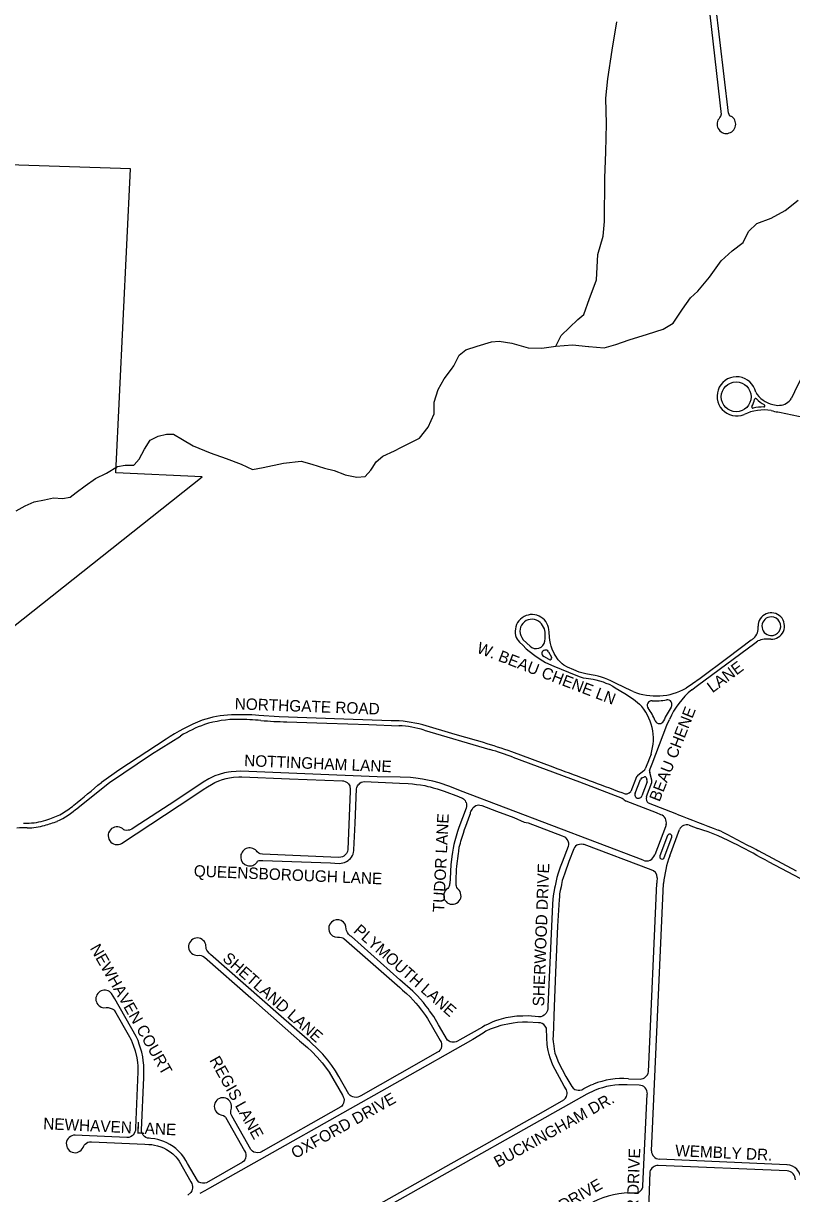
# Model space of a CAD drawing. Extents: x 0 to 712119, y 0 to 761125.
# Drawn here: x 662940 to 666284, y 723620 to 728717 of the extents above; entities that cross this region are included whole.
import ezdxf

# ---------------------------------------------------------------- set-up
doc = ezdxf.new("R2010")
doc.units = 0
for name, color, linetype in [('city boundary', 7, 'Continuous'), ('PAVED ROADS', 7, 'Continuous'), ('stream or creek', 7, 'Continuous'), ('street names', 7, 'Continuous')]:
    doc.layers.add(name, color=color, linetype=linetype)

msp = doc.modelspace()

# ---------------------------------------------------------------- linework, layer by layer
at = {"layer": 'city boundary'}
msp.add_lwpolyline([(661591.7, 725082), (661920.9, 725330.1), (662157.8, 725508.7), (662199.4, 725538.3), (663717.4, 726742.4), (663342.2, 726759.2), (663405.6, 728083), (662077.3, 728127.4), (662054.4, 728128.2), (662062.2, 728326.3), (661826.3, 728333.2), (661818.5, 728136.1), (660757.1, 728171.7), (660784.9, 728985.9), (660790.2, 729140.5), (660790.4, 729140.4), (660803.1, 729516.9), (659488, 729573.5)], dxfattribs=at)
at = {"layer": 'PAVED ROADS'}
for points in [[(665878, 729203.3), (665978.5, 728320.5)], [(666010, 728325.5), (665934.5, 728966.8)], [(665594.3, 725806.3), (665587, 725809.2), (665520.4, 725841.9), (665509, 725848), (665497.3, 725853.9), (665484.8, 725859.1), (665470.3, 725865.4), (665456.7, 725869.5), (665441.7, 725873.9), (665429.8, 725876.7), (665412.1, 725879.5), (665389.2, 725883.6), (665377.3, 725886.3), (665360.1, 725891.7), (665336, 725901.8), (665308.2, 725913), (665292.1, 725921.5), (665285.3, 725928), (665276.4, 725936.3), (665268.6, 725945.4), (665255.1, 725964.9), (665250.9, 725972.7), (665241.9, 725991.5), (665237.6, 726004.8), (665234.2, 726015.5), (665232.3, 726030.3), (665230.9, 726043.4), (665229.4, 726065.2), (665227.7, 726077.6), (665225.7, 726085.5), (665223.2, 726094.1)], [(665085.7, 726041.9), (665089.3, 726035), (665093.4, 726028.8), (665100, 726022.2), (665113.5, 726008.1), (665129.1, 725993.4), (665142.2, 725982.5), (665166.9, 725963.2), (665189.1, 725948), (665212.6, 725933.8), (665248.8, 725918), (665345.2, 725878.8), (665363.4, 725871.4), (665377.3, 725867.2), (665389.3, 725865.6), (665420.9, 725860.5), (665432.1, 725858.1), (665448.1, 725853.5), (665463.3, 725848.7), (665476.2, 725843.8), (665490.3, 725838.6), (665506.1, 725829.6), (665516.1, 725823.5), (665557.7, 725798.9), (665596.7, 725773.6), (665622.1, 725752.3)], [(665109.5, 726042.5), (665115.5, 726032), (665145.5, 726005)], [(665109.5, 726042.5), (665109.5, 726042.5)], [(666109, 726030.1), (666006.9, 725953.4), (665886.7, 725863.6), (665853.2, 725839.9), (665824.8, 725821)], [(665850, 725813.8), (665874.9, 725832.8), (666123.8, 726016.8), (666137.5, 726027)], [(665228.9, 725946.3), (665205.1, 725959.7)], [(665225.4, 725980.3), (665239.1, 725956.6)], [(665228.9, 725946.3), (665228.9, 725946.3)], [(665676.8, 725766.4), (665676.8, 725766.4)], [(664540.5, 725679.5), (664335, 725686.5), (664052.5, 725697), (663964.5, 725703)], [(664086, 725674.5), (664260.5, 725668.5), (664443.5, 725662.5), (664575, 725658)], [(664819.4, 725619.7), (664678.7, 725661.2)], [(665666.3, 725462.8), (665677.7, 725491.5), (665741.4, 725660.1), (665752.9, 725684.8)], [(663177.5, 725301), (663314.5, 725411), (663497, 725534), (663623, 725613)], [(664684.5, 725638.2), (664971.1, 725554.1)], [(663560.5, 725599), (663354.5, 725464.5), (663279, 725411)], [(665246.5, 725476.9), (665065.7, 725544.8)], [(665071.3, 725520.7), (665361, 725414.1), (665546.4, 725342.8)], [(665672.6, 725534.2), (665666.4, 725516.4), (665658.8, 725497.3), (665647.4, 725470.7)], [(665638.7, 725072.3), (664843.5, 725375), (664796.5, 725393), (664750, 725408.5), (664722, 725416), (664699.5, 725421), (664678, 725425.5), (664648.5, 725429.5), (664625, 725432.5), (664579.5, 725434.5), (664479.5, 725436), (664164.5, 725448.5), (663886, 725459.5), (663866.5, 725459), (663844, 725457), (663832.5, 725456), (663814.5, 725452.5), (663792, 725446), (663773, 725439), (663747, 725426.5), (663722, 725411.5), (663598.5, 725329.5), (663422, 725214), (663412, 725208), (663404, 725204.5), (663400.9, 725203.2), (663396, 725202.5), (663388.5, 725202), (663381, 725203.5), (663376.5, 725205)], [(665641.1, 725461.3), (665614.5, 725441.8)], [(665676.2, 725421.2), (665667.2, 725453.7)], [(663367, 725145), (663681.5, 725353), (663722, 725379.5), (663741.5, 725392), (663758, 725402), (663773, 725410.5), (663790.5, 725418), (663806, 725423.5), (663822.5, 725428.5), (663837, 725431.5), (663855, 725434), (663877.5, 725436), (663890, 725435.5), (664097.5, 725427), (664328.5, 725418.5), (664334, 725417.5), (664341, 725415.5), (664349.5, 725410.5), (664355, 725405), (664358.5, 725400), (664360.5, 725396), (664361.5, 725391.5), (664362.5, 725385), (664363, 725378.5), (664363, 725373.5), (664352.5, 725119), (664351, 725109.5), (664346.5, 725101.5), (664341, 725095), (664334.5, 725089.5), (664328.5, 725087), (664321.5, 725085), (664312, 725084), (663980, 725098), (663970, 725100), (663964.5, 725102.5), (663958, 725108), (663954, 725113)], [(663957, 725064), (663958.1, 725065.7), (663959.5, 725067.5), (663962, 725069), (663966.5, 725070.5), (663971, 725071), (663976.5, 725071.5), (663982.5, 725071), (664276.5, 725060), (664315, 725058.5), (664323.5, 725059), (664330.5, 725060.5), (664338, 725062.5), (664346.5, 725066), (664353.5, 725070.5), (664358.5, 725075), (664363.5, 725079.5), (664367.5, 725085), (664372, 725092), (664375, 725099), (664377, 725106.5), (664378.5, 725113.5), (664379, 725117.5), (664383.5, 725234), (664390, 725383), (664391.5, 725389), (664394, 725395.5), (664397, 725400.5), (664401, 725404), (664405, 725408), (664410, 725411.5), (664417.5, 725414), (664423, 725414.5), (664577.5, 725408), (664615, 725406), (664633.5, 725404.5), (664650.5, 725402.5), (664668, 725400), (664687, 725397), (664700, 725393.5), (664711, 725391), (664724, 725387.5), (664740.5, 725382.5), (664759, 725377), (664771.5, 725372.5), (664833.5, 725349.5), (664840.5, 725347), (664851, 725342.5), (664855.5, 725340), (664859, 725336.5), (664862.5, 725331.5), (664865, 725327), (664867, 725323), (664868.5, 725317.5), (664869.5, 725312), (664869, 725305.5), (664867.5, 725299.5), (664835.5, 725215), (664829, 725196.5), (664823.5, 725176.5), (664817.5, 725156.5), (664814, 725140), (664810.5, 725124.5), (664807.5, 725107.5), (664804.5, 725088), (664803, 725075), (664800.5, 725053.5), (664798, 724991.5), (664796, 724971.5), (664795.5, 724967.5), (664794.5, 724963), (664793, 724958.5), (664790, 724953), (664787, 724949.5), (664781, 724944.5)], [(665609.4, 725435), (665584.7, 725371.4)], [(665602.9, 725363.8), (665626.3, 725423.1)], [(665654.9, 725413.2), (665632.8, 725352.3)], [(665634.4, 725431.1), (665644.7, 725435)], [(665651.1, 725432.2), (665654.7, 725423.3)], [(665652.3, 725348.9), (665675.6, 725410.3)], [(665550.6, 725363.5), (665527.5, 725371.9)], [(664836.5, 724941.5), (664830.5, 724948), (664827.5, 724953.5), (664825, 724959), (664824, 724964), (664823.5, 724969), (664823.5, 724980), (664824.5, 724999), (664825, 725017), (664826, 725032), (664827, 725046.5), (664833.5, 725101.5), (664835, 725110.5), (664837.5, 725129), (664840, 725137.5), (664842.5, 725147), (664844.5, 725155.5), (664847, 725164), (664851.5, 725177), (664855.5, 725190), (664860.5, 725206.5), (664865.5, 725220.5), (664884, 725269), (664886, 725275), (664887, 725282), (664887.5, 725284), (664893.5, 725293), (664898.5, 725301.5), (664903.5, 725306.5), (664909, 725310.5), (664915, 725312.5), (664920.5, 725313), (664927, 725312.5), (664935, 725311), (665000, 725286), (665075, 725257.5), (665119.5, 725238.5), (665137.5, 725235.5), (665286, 725178), (665292.5, 725175), (665298, 725172), (665302.5, 725167), (665306.5, 725162), (665310, 725156), (665312.5, 725148.5), (665312.5, 725140.5), (665311, 725132.5), (665285, 725063.5), (665276.5, 725042), (665268, 725015), (665262.5, 724996.5), (665255, 724961), (665252, 724950.5), (665250, 724939.5), (665248, 724925.5), (665245.5, 724904), (665243, 724878.5), (665223.5, 724435), (665222.5, 724424.5), (665221, 724417.5), (665218.5, 724411), (665216, 724406), (665212, 724401.5), (665206.5, 724397), (665200, 724393), (665192.5, 724390.5), (665182.5, 724390.5), (665137.5, 724394), (665114, 724393), (665100, 724392.5), (665088.5, 724393), (665077.5, 724391.5), (665061, 724389), (665050, 724387.5), (665039.5, 724385), (665030, 724382.5), (665020, 724380), (665009.5, 724377), (664995.5, 724372.5), (664984, 724368), (664972.5, 724363), (664960.5, 724357), (664949, 724351.5), (664938.5, 724345.5), (664840, 724290), (664829.5, 724284), (664824, 724281.5), (664816.5, 724280), (664810, 724279.5), (664804.5, 724280), (664798.5, 724281.5), (664793, 724283.5), (664786.5, 724289), (664747.5, 724354.5), (664726, 724391), (664708.5, 724416.5), (664702, 724425.5), (664692, 724438.5), (664681, 724452.5), (664667.5, 724468), (664655, 724481.5), (664645, 724491.5), (664635, 724501.5), (664578.8, 724551.6), (664367.6, 724739.6), (664362.4, 724743.2), (664355, 724750.1), (664350.3, 724757.7), (664346.5, 724765.5), (664345, 724772)], [(665785.2, 725273), (665661.7, 725320.1)], [(665738.5, 725227.9), (665735, 725217.7), (665688.3, 725095.4)], [(665753.7, 725091.7), (665795.8, 725205.8)], [(665838.5, 725224.4), (665875.9, 725210.5)], [(665744.2, 725179.7), (665711.2, 725090.6)], [(665729.8, 725083.5), (665762.9, 725172.5)], [(665672.5, 725030), (665381.5, 725140.5), (665377.5, 725141), (665369.5, 725141.5), (665361.5, 725141), (665353.5, 725139.5), (665349, 725137.5), (665344, 725133), (665339.5, 725128), (665336.5, 725122), (665314.5, 725067), (665297, 725015.5), (665290, 724995.5), (665286, 724983.5), (665282, 724967), (665280.5, 724956.5), (665276.5, 724939.5), (665274, 724926), (665273.5, 724911.5), (665272, 724901.5), (665265.5, 724785.5), (665256.5, 724583), (665250.5, 724434.5), (665246, 724307.5), (665245.5, 724293.5), (665246.5, 724280.5), (665248.5, 724263), (665251, 724248.5), (665254, 724232), (665258, 724221.5), (665270, 724191), (665302, 724130.5), (665327, 724086.5), (665333, 724079), (665341, 724074), (665347.5, 724072), (665355, 724070.5), (665363, 724070), (665371.5, 724072.5), (665379.5, 724077.5), (665388.5, 724082.5), (665412.2, 724093.3), (665421.3, 724097.2)], [(666305.7, 725024), (666140.4, 725112.3)], [(666182.3, 725066.5), (666350.6, 724977.3), (666485.1, 724907.2)], [(665661, 724150.6), (665698.1, 724972.6)], [(665674.3, 723806.7), (665726.8, 724970.5)], [(664306.5, 724736.5), (664311.1, 724736.6), (664316.2, 724736.9), (664324.1, 724735.9), (664330.4, 724734), (664335.3, 724731.6), (664578.6, 724517.5), (664590.5, 724506), (664607.5, 724491), (664623, 724476.5), (664636, 724462.5), (664648, 724450), (664658.5, 724438), (664673, 724419.5), (664681.5, 724408), (664691, 724395), (664699.5, 724382.5), (664749, 724296.5), (664754.5, 724286.5), (664758, 724279.5), (664760, 724274), (664760.5, 724267), (664760, 724260.5), (664758.5, 724254), (664756.5, 724249.5), (664753.5, 724244.5), (664749, 724239.5), (664743.2, 724235.6), (664577.8, 724141.4)], [(664577.8, 724141.4), (664409.5, 724046.2), (664403, 724042.9), (664395.7, 724040.1), (664389.2, 724038.9), (664380.2, 724039.5), (664373.3, 724041.2), (664367.2, 724043.7), (664361.7, 724047.8), (664357.2, 724052.7), (664312.7, 724130.5), (664298, 724154.1), (664282, 724177.7), (664264.7, 724200.5), (664243.3, 724226.6), (664224.6, 724246.5), (664186.8, 724282.2), (664049.7, 724402.2), (663754.4, 724661.7), (663748, 724667.2), (663742.4, 724673.9), (663738.3, 724680.2), (663735.8, 724686.8), (663735.1, 724692.3), (663734.3, 724700.1), (663733.5, 724704.5)], [(663698, 724657.5), (663707.5, 724658), (663714, 724657), (663720.5, 724654.5), (663727.5, 724650.5), (663930, 724472.5), (664142, 724286), (664176, 724257), (664195, 724239), (664219, 724214), (664240, 724189.5), (664255.5, 724170), (664270.5, 724148.5), (664329, 724048), (664332, 724041.5), (664334.5, 724035.5), (664335.5, 724028.5), (664334.5, 724021), (664333, 724013.5), (664330, 724007.5), (664325.5, 724001.5), (664322, 723997.5), (663984, 723806.5), (663979.5, 723803.5), (663970.5, 723799.5), (663960, 723798), (663951, 723798.5), (663943, 723801), (663936.5, 723804.5), (663929.5, 723812), (663847, 723958), (663843, 723967.5), (663842, 723972), (663842, 723977), (663842, 723981), (663843.5, 723986), (663844.9, 723992), (663845.5, 723996)], [(663799, 723963.5), (663804, 723962), (663810.5, 723959.5), (663816, 723956), (663819.5, 723953), (663902.5, 723806), (663906, 723798.5), (663908, 723791), (663908, 723782.5), (663906.5, 723774.5), (663903.5, 723767.5), (663899, 723761.5), (663893.5, 723756.5), (663736.5, 723667), (663729, 723665), (663719.5, 723665), (663711.5, 723666.5), (663703.5, 723670.5), (663697, 723676.5), (663654.5, 723750.5), (663647, 723764), (663637.5, 723778.5), (663627.5, 723792), (663615, 723805), (663603.5, 723816), (663592, 723824.5), (663577.5, 723834), (663564.5, 723841.5), (663551, 723847), (663538.5, 723851.5), (663525, 723856), (663512, 723858.5), (663494.5, 723860.5), (663487, 723861), (663480.5, 723862), (663473, 723864.5), (663466.5, 723869), (663461.5, 723875), (663456.5, 723883), (663454, 723890), (663453.5, 723896.5), (663464, 724125), (663464.5, 724143), (663464.5, 724163.5), (663464, 724179.5), (663461.5, 724200), (663459, 724215.5), (663454.5, 724236), (663450, 724253), (663444, 724270.5), (663438.5, 724286.5), (663430.5, 724304), (663337, 724468.5), (663323.5, 724491)], [(663290, 724429.5), (663299.5, 724430), (663308.5, 724430), (663318, 724428), (663326, 724425), (663331.5, 724422), (663335, 724418.5), (663342, 724407.5), (663396, 724313), (663408, 724290), (663418, 724267), (663425.5, 724242.5), (663433, 724211.5), (663436, 724191), (663437.5, 724177), (663438, 724163.5), (663438, 724151), (663428, 723906), (663427.5, 723901), (663427, 723895), (663425, 723888.5), (663422, 723882), (663418, 723876.5), (663412.5, 723871.5), (663405.5, 723867.5), (663398.5, 723865), (663390, 723864.5), (663196, 723873.5), (663164.5, 723875)], [(664227.7, 723427.6), (664578.6, 723624.7), (664779.3, 723738), (664947.4, 723832.9), (665098.1, 723918.1), (665203.8, 723978), (665292.8, 724028.9), (665299.3, 724035.7), (665304.4, 724043.1), (665306.2, 724048.5), (665307.9, 724055.2), (665307.6, 724061), (665306.5, 724066.8), (665304.4, 724071.3), (665294.8, 724088.5), (665244.9, 724180), (665239.1, 724194.9), (665233.1, 724211), (665228.7, 724226.2), (665224.8, 724242.6), (665222.1, 724258.3), (665220.2, 724270.5), (665218.2, 724296.6), (665217.3, 724340.1), (665211.6, 724349.8), (665205.9, 724356.2), (665198.6, 724360.5), (665191.5, 724363.1), (665183.1, 724364.3), (665134.2, 724366.4), (665112.2, 724366.2), (665090.4, 724364.6), (665071.7, 724362.6), (665048.9, 724358.5), (665033.6, 724355.4), (665019.1, 724351.7), (664998, 724344.7), (664972.4, 724335.6), (664953.5, 724327), (664941.4, 724319.1), (664896.1, 724291.1), (664578.6, 724111.6), (663749.1, 723643.1), (663729.6, 723632.3), (663707.8, 723619.7)], [(665620.4, 724092.2), (665568.7, 724093.7)], [(665573.9, 724120.5), (665624.6, 724118.8)], [(665392.5, 724053.4), (664578.7, 723594.7), (664190.1, 723375.9), (664170.3, 723364), (664155.6, 723353.4), (664137, 723340), (664119, 723324), (664102.5, 723306.5), (664085.5, 723286.5), (664067.5, 723261.5), (664048.5, 723230), (663998, 723144.5), (663986, 723124.5), (663965, 723088.5)], [(665426.5, 724069.6), (665392.5, 724053.4)], [(665637.4, 723653.9), (665656.3, 724053.7)], [(663202, 723827.5), (663204, 723831), (663208.5, 723835.5), (663214, 723839.5), (663220.5, 723843.5), (663227, 723845), (663235.5, 723845), (663468, 723835), (663486, 723834), (663498, 723833.5), (663510.5, 723831.5), (663523.5, 723828.5), (663537.5, 723824), (663549.5, 723819), (663562.5, 723812.5), (663578.5, 723802.5), (663590.5, 723793), (663603, 723780.5), (663611, 723771.5), (663617.5, 723761.5), (663668.5, 723671.5), (663673, 723663.5), (663675, 723658.5), (663676, 723650.5), (663676.5, 723644), (663675, 723638), (663673, 723631.5), (663668, 723625), (663655.5, 723612.5)], [(666264.5, 723744.9), (665708.7, 723769.7)], [(666265, 723718.9), (665704.1, 723743)], [(665666.9, 723714.6), (665655.3, 723384.7)], [(665666.9, 723714.6), (665666.9, 723714.6)]]:
    msp.add_lwpolyline(points, dxfattribs=at)
msp.add_circle((666043.5, 727090.5), 65, dxfattribs=at)
for centre, radius, start, end in [((666000.6, 728278), 40.4, 137.1515, 61.3938), ((665957.9, 728321.4), 20.6, 309.3905, 357.4794), ((666022.7, 728325.9), 12.7, 181.8007, 257.8105), ((666923.8, 726824.5), 689.9, 78.6949, 157.9022), ((666045.2, 727092.6), 85.2, 12.1306, 292.6218), ((666128, 727078.8), 5, 42.5223, 171.7827), ((666224.9, 727166.1), 111.2, 209.9711, 258.663), ((666227.3, 727169.8), 129.7, 222.5223, 241.7194), ((666229.4, 727118.3), 64.9, 272.7195, 328.067), ((666165.6, 726823.3), 209.9, 81.8017, 114.6633), ((666116.2, 727046.2), 5, 148.2635, 281.8121), ((666043.9, 727090.9), 80, 328.2635, 351.7827), ((666164.3, 726816), 230.2, 90.2046, 101.8121), ((666163.5, 727051.2), 5, 270.2046, 61.7194), ((666242.4, 727173.8), 150.3, 251.8067, 263.3414), ((666225.1, 727117.2), 64.1, 249.8387, 276.6289), ((666802.3, 729616.7), 2655.7, 257.4439, 262.2888), ((665154.2, 726068.6), 73.5, 20.2772, 201.292), ((665153.4, 726069.9), 51.8, 45.8359, 211.9191), ((666196.1, 726092), 57.6, 267.9322, 181.0447), ((666196.1, 726091.3), 40.7, 88.743, 265.6701), ((666196.5, 726091.3), 40.7, 265.116, 89.297), ((665144.6, 726056.8), 67.4, 19.6895, 48.1701), ((665091.4, 726048.1), 120.8, 349.192, 15.0502), ((666082.8, 726081.9), 56.4, 310.6912, 9.3262), ((665172.5, 726031.9), 38.1, 224.9721, 350.2915), ((666164, 725976), 77.1, 125.1578, 135.5405), ((666179.9, 725923.8), 111.6, 82.7637, 112.3592), ((665212.4, 725972.8), 15, 30.1252, 240.809), ((665232.6, 725952.9), 7.5, 240.809, 30.1252), ((665693.7, 726061.7), 274.1, 248.7291, 298.5777), ((666056.7, 725557.2), 329.5, 128.8663, 157.2324), ((665675.7, 725746.4), 20, 87.0202, 217.4476), ((665691.7, 726053.5), 287.5, 267.0202, 279.7097), ((665743.6, 725750.4), 20, 326.1513, 99.7097), ((663855.3, 725297.1), 408, 91.4517, 109.5961), ((663884.6, 724498.1), 1207.6, 86.2046, 91.8777), ((665460.8, 725600.1), 221.8, 342.7231, 43.3334), ((665486.2, 725601.3), 218.7, 21.0046, 37.4476), ((666065.8, 725534.3), 368, 146.1513, 156.8481), ((663992.5, 724964.2), 767.9, 110.9066, 124.2362), ((663918.5, 725127.8), 568.1, 109.5888, 121.3379), ((663871.7, 725215.8), 469.7, 89.4745, 107.8141), ((663851.9, 724091.9), 1593.8, 85.6073, 89.1345), ((664147.3, 727698.6), 2025, 265.0912, 268.2659), ((664543.8, 725174.5), 505, 74.5114, 90.378), ((664557, 725246), 412.4, 71.989, 87.5019), ((665709.1, 725686.9), 20, 201.0046, 336.8481), ((663736.1, 721611.2), 4152.3, 71.3237, 74.8769), ((664513.8, 724019.5), 1601.4, 69.6261, 73.4059), ((655135.2, 698013.6), 29265.6, 69.20033, 69.7877), ((665620.8, 725481.5), 28.7, 315.164, 337.853), ((665678.7, 725459.4), 12.9, 164.5887, 206.5655), ((655600, 734550), 11936.8, 309.29027, 310.03851), ((665625, 725428.5), 17, 128.28, 157.5438), ((665639.3, 725418), 14, 110.4689, 158.4948), ((665646.4, 725430.3), 5, 22.3959, 110.4689), ((665641.8, 725418), 14, 340.0033, 22.3959), ((665641.1, 725417.8), 35.3, 347.6675, 5.4105), ((665562.4, 725390.1), 29.1, 246.0583, 320.0567), ((665617.8, 725358), 16, 158.499, 339.2273), ((665675.2, 725340.4), 24.4, 159.7824, 236.4009), ((662873, 725665.6), 475.1, 296.7778, 309.8687), ((662886, 725642.1), 428.7, 300.7174, 309.551), ((665592, 725388.3), 64.4, 224.8965, 244.9294), ((661850.6, 715732.3), 10291.2, 67.94565, 68.84466), ((662945.8, 725537.9), 305, 273.6093, 289.2809), ((662775.1, 726010.1), 807.1, 289.6475, 294.1241), ((665703, 725236), 36.4, 347.1095, 71.095), ((671984.7, 741072.2), 16972, 248.57533, 249.22664), ((662940.5, 724565.6), 647.1, 88.5858, 92.6597), ((662952.2, 725373.3), 140.4, 264.7906, 275.2094), ((662953.4, 725486.3), 273.8, 270.6447, 286.6765), ((662759, 726177), 991.4, 285.982, 289.3182), ((663347.5, 725178.8), 39, 42.0676, 299.9381), ((665827.9, 725190.3), 35.7, 72.83, 154.1482), ((665548.6, 724184.6), 1076.8, 62.2309, 72.3086), ((662553.5, 718441.5), 7573.9, 61.73288, 63.227), ((665753.6, 725176.1), 10, 339.019, 159.019), ((663924.8, 725086.6), 39.3, 42.1162, 324.8909), ((665653.4, 725105.4), 36.3, 245.9894, 344.0242), ((661268.3, 716075.8), 10246, 61.34054, 62.17801), ((665720.5, 725087.1), 10, 159.019, 339.019), ((666201, 724928.9), 475.9, 159.9934, 174.9833), ((665666.6, 724998.4), 32.2, 355.775, 79.398), ((666555.1, 724964.3), 857, 177.8823, 179.4484), ((664807.4, 724917.6), 37.7, 134.4021, 39.4098), ((664306.9, 724774.7), 38.2, 355.9419, 269.415), ((663696.7, 724695.4), 37.9, 13.8839, 271.9872), ((663293.2, 724467.6), 38.2, 37.7172, 265.1272), ((665624.4, 724155.8), 37, 270.1682, 351.8693), ((665552.6, 723749.2), 371.9, 86.7127, 110.6759), ((665552.9, 723755.6), 338.5, 87.3333, 111.9268), ((665621, 724056.7), 35.5, 355.0797, 90.8875), ((663808.1, 724000), 37.6, 353.9288, 255.9725), ((663164.6, 723836.6), 38.4, 90.1981, 346.3823), ((665710.2, 723805.5), 35.8, 177.971, 267.6438), ((665706.2, 723701.6), 41.4, 92.9796, 161.7506), ((666262.9, 723682.4), 62.5, 0.2291, 88.502), ((666262.3, 723679.9), 39.1, 359.6671, 85.9797), ((665585.6, 723258.8), 364, 87.1942, 117.2125), ((665603.8, 723656.1), 33.7, 269.347, 356.3108)]:
    msp.add_arc(centre, radius, start, end, dxfattribs=at)
at = {"layer": 'stream or creek'}
for points in [[(665258, 727311), (665281.7, 727357.3), (665353.6, 727427.6), (665380.1, 727449.5), (665405.2, 727518.8), (665433.1, 727595.5), (665434.3, 727600.2), (665441, 727710.4), (665464.5, 727790.1), (665469.2, 727854.2), (665471.9, 728042.8), (665475.4, 728157.3), (665478.6, 728279.2), (665475.5, 728391.7), (665484.8, 728476.1), (665503.5, 728601.1), (665523.9, 728724.5)], [(665258, 727311), (665329.9, 727317.3), (665400.1, 727309.5), (665402, 727309.3), (665468.9, 727303.3), (665518.9, 727318.9), (665576.7, 727339.2), (665656.4, 727364.1), (665725.1, 727384.5), (665768.9, 727411), (665809.5, 727472), (665843.9, 727522), (665876.7, 727550.1), (665926.7, 727611), (665978.3, 727682.9), (666025.1, 727726.7), (666073.6, 727762.6), (666097, 727811), (666133, 727845.4), (666195.4, 727868.8), (666256.4, 727901.7), (666312.6, 727947)], [(662908, 726594.3), (662947, 726616.3), (662986, 726633.3), (663031, 726642.3), (663071, 726650.3), (663110, 726647.3), (663143, 726653.3), (663169, 726674.3), (663209, 726702.3), (663254, 726735.3), (663301, 726758.3), (663349, 726786.3), (663383, 726792.3), (663408.9, 726793), (663421, 726793.3), (663421.9, 726794.4), (663443, 726819.3), (663467, 726862.3), (663491, 726901.3), (663527, 726919.3), (663563, 726928.3), (663593, 726927.3), (663632, 726905.3), (663679, 726877.3), (663752, 726846.3), (663822, 726822.3), (663888, 726797.3), (663937.6, 726773.6), (663982.9, 726782.9), (664072, 726801.7), (664148.6, 726809.5), (664195.5, 726797), (664250.2, 726779.8), (664292.3, 726768.9), (664337.1, 726751.5), (664340.8, 726750.1), (664390.7, 726740.7), (664428.3, 726743.9), (664451.7, 726770.4), (664457.8, 726780.3), (664475.2, 726807.9), (664504.8, 726831.3), (664554.8, 726854.8), (664583.4, 726869.7), (664617.3, 726887.6), (664664.2, 726911), (664701.7, 726957.9), (664728.3, 727015.7), (664728.3, 727067.3), (664745.5, 727122), (664772, 727168.9), (664803.6, 727211), (664814.2, 727225.1), (664837.6, 727272), (664865.8, 727295.4), (664915.8, 727311), (664978.3, 727329.8), (665011.1, 727332.9), (665065.8, 727323.5), (665137.6, 727303.2), (665197, 727301.7), (665258, 727311)]]:
    msp.add_lwpolyline(points, dxfattribs=at)

# ---------------------------------------------------------------- texts
at = {"layer": 'street names'}
for s, rotation, p in [('W. BEAU CHENE LN', 339, (664909.8, 725977.4)), ('LANE', 36.5, (665939.6, 725798.9)), ('NORTHGATE ROAD', 357.8908, (663859, 725729.4)), ('BEAU CHENE', 68.5496, (665709.4, 725323.7)), ('NOTTINGHAM LANE', 357.588, (663900, 725482.1)), ('TUDOR LANE', 87.3139, (664771.9, 724844.7)), ('QUEENSBOROUGH LANE', 357.5882, (663680.6, 725001.2)), ('SHERWOOD DRIVE', 87.8862, (665206.8, 724434.6)), ('PLYMOUTH LANE', 318.5969, (664373.3, 724760.2)), ('NEWHAVEN COURT', 299.7986, (663227.6, 724689)), ('SHETLAND LANE', 318.597, (663802.9, 724638.3)), ('REGIS LANE', 299.2712, (663748.3, 724201.5)), ('OXFORD DRIVE', 29.2713, (664122.9, 723770.3)), ('BUCKINGHAM DR.', 29.2713, (665005.8, 723732.1)), ('NEWHAVEN LANE', 357.3137, (663024.9, 723900.7)), ('WEMBLY DR.', 357.2674, (665776.8, 723783.6)), ('WINDSOR DRIVE', 87.8862, (665605.7, 723271.3)), ('DOVER DRIVE', 29.9245, (665066.7, 723414.9))]:
    msp.add_text(s, height=50, rotation=rotation, dxfattribs=at).set_placement(p)

doc.saveas('drawing.dxf')
